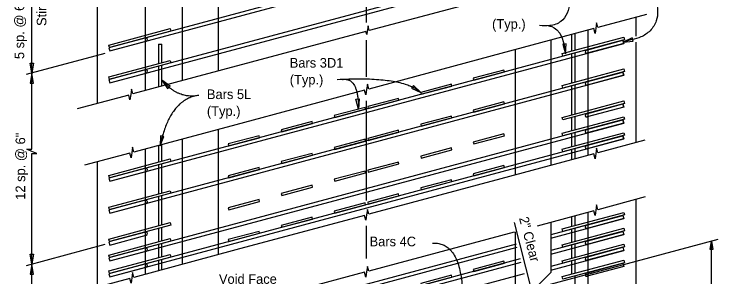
# Model space of a CAD drawing. Extents: x 0.8 to 30.4, y 0.3 to 18.9.
# Drawn here: x 19.16 to 30.22, y 8.31 to 12.43 of the extents above; entities that cross this region are included whole.
import ezdxf

# ---------------------------------------------------------------- set-up
doc = ezdxf.new("R2010")
doc.units = 0
for name, color, linetype in [('BeamConc', 7, 'Continuous'), ('BeamConc_h', 7, 'Continuous'), ('CL_Major', 7, 'Continuous'), ('Dimension', 7, 'Continuous'), ('Rebar', 7, 'Continuous'), ('Rebar_h', 7, 'Continuous'), ('TextStructures', 7, 'Continuous')]:
    doc.layers.add(name, color=color, linetype=linetype)

msp = doc.modelspace()

# ---------------------------------------------------------------- linework, layer by layer
at = {"layer": 'BeamConc'}
for p, q in [((20.473, 11.032), (20.473, 17.385)), ((21.807, 11.389), (21.807, 17.385)), ((28.932, 12.382), (28.932, 12.087)), ((27.598, 12.025), (27.598, 10.059)), ((28.932, 11.996), (28.932, 10.416)), ((21.807, 8.507), (21.807, 10.474)), ((20.473, 8.15), (20.473, 10.117)), ((28.932, 9.524), (28.932, 6.615)), ((27.598, 9.166), (27.598, 8.378)), ((27.598, 8.378), (27.348, 8.128))]:
    msp.add_line(p, q, dxfattribs=at)
at = {"layer": 'BeamConc_h'}
for p, q in [((22.369, 17.385), (22.369, 11.54)), ((21.223, 17.303), (21.223, 11.233)), ((28.182, 10.215), (28.182, 12.182)), ((27.036, 11.875), (27.036, 9.908)), ((22.369, 10.625), (22.369, 8.658)), ((21.223, 10.318), (21.223, 8.351)), ((28.182, 6.351), (28.182, 9.323)), ((27.036, 9.016), (27.036, 6.044))]:
    msp.add_line(p, q, dxfattribs=at)
at = {"layer": 'CL_Major'}
for p, q in [((24.702, 12.302), (24.702, 17.235)), ((24.702, 11.448), (24.702, 12.027)), ((24.702, 9.507), (24.702, 11.073)), ((24.702, 8.597), (24.702, 9.109))]:
    msp.add_line(p, q, dxfattribs=at)
at = {"layer": 'Dimension'}
for p, q in [((20.588, 11.816), (19.35, 11.485)), ((27.293, 8.113), (27.026, 9.166)), ((30.224, 8.898), (27.507, 8.17)), ((30.124, 6.872), (30.124, 8.872)), ((20.588, 8.816), (19.35, 8.485))]:
    msp.add_line(p, q, dxfattribs=at)
for points in [[(19.442, 11.509), (19.442, 17.646)], [(26.782, 12.723), (24.745, 12.177), (24.725, 12.252), (24.713, 12.168), (24.705, 12.116)], [(29.103, 12.428), (28.337, 12.223), (28.317, 12.298), (28.305, 12.214), (28.292, 12.131), (28.272, 12.206), (26.81, 11.814)], [(24.705, 12.116), (24.692, 12.163), (21.987, 11.438)], [(26.81, 11.814), (24.735, 11.258), (24.715, 11.333), (24.702, 11.25), (24.69, 11.166), (24.67, 11.241), (22.648, 10.699)], [(19.442, 8.509), (19.442, 10.246), (19.519, 10.246), (19.442, 10.28), (19.364, 10.314), (19.442, 10.314), (19.442, 11.509)], [(21.987, 11.438), (21.028, 11.181), (21.008, 11.256), (20.996, 11.172), (20.983, 11.089), (20.963, 11.164), (20.152, 10.946)], [(22.648, 10.699), (21.045, 10.27), (21.025, 10.345), (21.013, 10.261), (21, 10.178), (20.98, 10.253), (20.268, 10.062)], [(29.074, 10.454), (28.337, 10.257), (28.317, 10.331), (28.305, 10.248), (28.292, 10.164), (28.272, 10.239), (26.81, 9.847)], [(26.81, 9.847), (24.735, 9.292), (24.715, 9.367), (24.702, 9.283), (24.69, 9.199), (24.67, 9.274), (22.648, 8.733)], [(29.083, 9.564), (28.337, 9.364), (28.317, 9.439), (28.305, 9.356), (28.292, 9.272), (28.272, 9.347), (27.382, 9.108)], [(27.023, 9.012), (24.735, 8.399), (24.715, 8.474), (24.702, 8.391), (24.69, 8.307), (24.67, 8.382), (22.648, 7.84)], [(22.648, 8.733), (21.045, 8.303), (21.025, 8.378), (21.013, 8.295), (21, 8.211), (20.98, 8.286), (20.26, 8.093)], [(19.442, 3.464), (19.442, 7.546), (19.519, 7.546), (19.442, 7.58), (19.364, 7.614), (19.442, 7.614), (19.442, 8.509)]]:
    msp.add_lwpolyline(points, dxfattribs=at)
for points in [[(28.735, 11.996), (28.892, 12.012), (28.878, 12.063)], [(27.828, 11.812), (27.84, 11.97), (27.788, 11.965)], [(19.442, 11.509), (19.415, 11.666), (19.468, 11.666)], [(19.442, 11.509), (19.415, 11.353), (19.468, 11.353)], [(21.484, 11.399), (21.574, 11.269), (21.612, 11.306)], [(25.553, 11.206), (25.438, 11.315), (25.408, 11.271)], [(24.577, 10.945), (24.534, 11.097), (24.587, 11.103)], [(21.455, 10.366), (21.513, 10.514), (21.461, 10.525)], [(30.124, 8.871), (30.146, 8.738), (30.102, 8.738)], [(19.442, 8.509), (19.415, 8.666), (19.468, 8.666)], [(19.442, 8.509), (19.415, 8.353), (19.468, 8.353)]]:
    msp.add_lwpolyline(points, close=True, dxfattribs=at)
for points in [[(27.817, 13.338), (27.899, 12.616), (27.755, 12.319), (27.582, 12.253), (27.422, 12.253)], [(29.419, 12.835), (29.343, 12.835), (29.255, 12.772), (29.255, 12.645), (29.255, 12.328), (29.157, 12.174), (29.014, 12.076), (28.873, 12.034), (28.735, 11.996)]]:
    msp.add_spline(points, degree=3, dxfattribs=at)
for points, degree in [([(27.562, 12.248), (27.597, 12.246), (27.791, 12.231), (27.828, 11.812)], 3), ([(22.065, 11.158), (21.742, 11.094), (21.484, 11.399)], 2), ([(24.239, 11.409), (25.273, 11.465), (25.553, 11.206)], 2), ([(24.323, 11.409), (24.571, 11.449), (24.577, 10.945)], 2), ([(22.065, 11.158), (21.61, 11.103), (21.455, 10.366)], 2), ([(25.737, 8.841), (26.278, 8.87), (26.204, 7.649)], 2)]:
    msp.add_open_spline(points, degree=degree, dxfattribs=at)
at = {"layer": 'Rebar'}
for p, q in [((20.65, 11.949), (21.616, 12.208)), ((21.616, 12.208), (21.627, 12.168)), ((21.225, 12.06), (20.651, 11.906)), ((21.627, 12.168), (20.661, 11.909)), ((27.777, 11.814), (28.743, 12.073)), ((27.921, 12.112), (27.921, 11.853)), ((27.973, 12.126), (27.973, 11.867)), ((28.743, 12.073), (28.754, 12.033)), ((20.661, 11.909), (20.65, 11.949)), ((20.665, 11.856), (21.239, 12.01)), ((21.432, 11.964), (21.432, 11.659)), ((21.432, 11.964), (21.484, 11.964)), ((21.484, 11.673), (21.484, 11.964)), ((28.754, 12.033), (27.788, 11.774)), ((28.156, 11.871), (28.73, 12.025)), ((28.744, 11.975), (28.17, 11.821)), ((28.73, 12.025), (28.744, 11.975)), ((20.651, 11.906), (20.665, 11.856)), ((27.788, 11.774), (27.777, 11.814)), ((27.921, 11.81), (27.921, 11.353)), ((27.973, 11.824), (27.973, 11.367)), ((20.65, 11.449), (21.616, 11.708)), ((21.627, 11.668), (20.661, 11.409)), ((21.484, 11.303), (21.484, 11.629)), ((21.616, 11.708), (21.627, 11.668)), ((21.225, 11.56), (20.651, 11.406)), ((20.665, 11.356), (21.239, 11.51)), ((21.432, 11.616), (21.432, 11.289)), ((27.777, 11.314), (28.743, 11.573)), ((28.754, 11.533), (27.788, 11.274)), ((28.156, 11.371), (28.73, 11.525)), ((28.73, 11.525), (28.744, 11.475)), ((28.743, 11.573), (28.754, 11.533)), ((20.661, 11.409), (20.65, 11.449)), ((20.651, 11.406), (20.665, 11.356)), ((28.744, 11.475), (28.17, 11.321)), ((27.788, 11.274), (27.777, 11.314)), ((27.921, 11.31), (27.921, 10.853)), ((27.973, 11.324), (27.973, 10.867)), ((27.777, 10.814), (28.743, 11.073)), ((28.743, 11.073), (28.754, 11.033)), ((28.754, 11.033), (27.788, 10.774)), ((28.156, 10.871), (28.73, 11.025)), ((28.744, 10.975), (28.17, 10.821)), ((28.73, 11.025), (28.744, 10.975)), ((27.777, 10.564), (28.743, 10.823)), ((27.788, 10.774), (27.777, 10.814)), ((28.754, 10.783), (27.788, 10.524)), ((27.921, 10.81), (27.921, 10.603)), ((27.973, 10.824), (27.973, 10.617)), ((28.156, 10.621), (28.73, 10.775)), ((28.73, 10.775), (28.744, 10.725)), ((28.743, 10.823), (28.754, 10.783)), ((28.744, 10.725), (28.17, 10.571)), ((27.777, 10.314), (28.743, 10.573)), ((27.788, 10.524), (27.777, 10.564)), ((28.754, 10.533), (27.788, 10.274)), ((27.921, 10.56), (27.921, 10.353)), ((27.973, 10.574), (27.973, 10.367)), ((28.156, 10.371), (28.73, 10.525)), ((28.73, 10.525), (28.744, 10.475)), ((28.743, 10.573), (28.754, 10.533)), ((28.744, 10.475), (28.17, 10.321)), ((21.432, 10.373), (21.432, 10.113)), ((21.484, 10.127), (21.484, 10.387)), ((27.788, 10.274), (27.777, 10.314)), ((27.921, 10.31), (27.921, 10.145)), ((27.973, 10.324), (27.973, 10.159)), ((20.65, 9.903), (21.616, 10.162)), ((21.627, 10.122), (20.661, 9.863)), ((21.432, 10.07), (21.432, 9.613)), ((21.484, 9.627), (21.484, 10.083)), ((21.616, 10.162), (21.627, 10.122)), ((21.225, 10.014), (20.651, 9.86)), ((20.665, 9.81), (21.239, 9.964)), ((20.661, 9.863), (20.65, 9.903)), ((20.651, 9.86), (20.665, 9.81)), ((20.65, 9.403), (21.616, 9.662)), ((21.616, 9.662), (21.627, 9.622)), ((21.225, 9.514), (20.651, 9.36)), ((21.627, 9.622), (20.661, 9.363)), ((21.432, 9.57), (21.432, 9.113)), ((21.484, 9.127), (21.484, 9.583)), ((20.665, 9.31), (21.239, 9.464)), ((20.661, 9.363), (20.65, 9.403)), ((20.651, 9.36), (20.665, 9.31)), ((27.777, 9.064), (28.743, 9.323)), ((28.743, 9.323), (28.754, 9.283)), ((28.754, 9.283), (27.788, 9.024)), ((27.921, 9.253), (27.921, 9.103)), ((27.973, 9.267), (27.973, 9.117)), ((28.156, 9.121), (28.73, 9.275)), ((28.744, 9.225), (28.17, 9.071)), ((28.73, 9.275), (28.744, 9.225)), ((20.65, 8.903), (21.616, 9.162)), ((21.627, 9.122), (20.661, 8.863)), ((21.484, 8.877), (21.484, 9.083)), ((21.616, 9.162), (21.627, 9.122)), ((27.777, 8.814), (28.743, 9.073)), ((27.973, 9.074), (27.973, 8.867)), ((28.743, 9.073), (28.754, 9.033)), ((21.225, 9.014), (20.651, 8.86)), ((20.665, 8.81), (21.239, 8.964)), ((21.432, 9.07), (21.432, 8.863)), ((27.788, 9.024), (27.777, 9.064)), ((28.754, 9.033), (27.788, 8.774)), ((27.921, 9.06), (27.921, 8.853)), ((28.156, 8.871), (28.73, 9.025)), ((28.744, 8.975), (28.17, 8.821)), ((28.73, 9.025), (28.744, 8.975)), ((20.65, 8.653), (21.616, 8.912)), ((20.661, 8.863), (20.65, 8.903)), ((20.651, 8.86), (20.665, 8.81)), ((21.627, 8.872), (20.661, 8.613)), ((21.616, 8.912), (21.627, 8.872)), ((21.225, 8.764), (20.651, 8.61)), ((21.432, 8.82), (21.432, 8.613)), ((21.484, 8.627), (21.484, 8.833)), ((27.777, 8.564), (28.743, 8.823)), ((27.788, 8.774), (27.777, 8.814)), ((28.754, 8.783), (27.788, 8.524)), ((27.921, 8.81), (27.921, 8.603)), ((27.973, 8.824), (27.973, 8.617)), ((28.156, 8.621), (28.73, 8.775)), ((28.73, 8.775), (28.744, 8.725)), ((28.743, 8.823), (28.754, 8.783)), ((20.65, 8.403), (21.616, 8.662)), ((20.661, 8.613), (20.65, 8.653)), ((20.665, 8.56), (21.239, 8.714)), ((21.616, 8.662), (21.627, 8.622)), ((28.744, 8.725), (28.17, 8.571)), ((20.651, 8.61), (20.665, 8.56)), ((21.627, 8.622), (20.661, 8.363)), ((21.432, 8.57), (21.432, 8.407)), ((21.484, 8.421), (21.484, 8.583)), ((27.777, 8.314), (28.743, 8.573)), ((27.788, 8.524), (27.777, 8.564)), ((28.754, 8.533), (27.788, 8.274)), ((27.921, 8.56), (27.921, 8.353)), ((27.973, 8.574), (27.973, 8.367)), ((28.156, 8.371), (28.73, 8.525)), ((28.73, 8.525), (28.744, 8.475)), ((28.743, 8.573), (28.754, 8.533)), ((21.225, 8.514), (20.651, 8.36)), ((20.665, 8.31), (21.239, 8.464)), ((28.744, 8.475), (28.17, 8.321)), ((20.661, 8.363), (20.65, 8.403)), ((20.651, 8.36), (20.665, 8.31)), ((27.788, 8.274), (27.777, 8.314)), ((27.973, 8.324), (27.973, 8.018))]:
    msp.add_line(p, q, dxfattribs=at)
for points in [[(26.386, 11.397), (26.869, 11.526), (26.861, 11.557), (26.378, 11.427)], [(25.561, 11.176), (26.044, 11.305), (26.036, 11.335), (25.553, 11.206)], [(24.728, 10.953), (25.21, 11.082), (25.202, 11.112), (24.719, 10.983)], [(24.202, 10.812), (24.685, 10.941), (24.677, 10.971), (24.194, 10.842)], [(26.386, 10.897), (26.869, 11.026), (26.861, 11.057), (26.378, 10.927)], [(23.369, 10.589), (23.852, 10.718), (23.844, 10.748), (23.361, 10.619)], [(25.561, 10.676), (26.044, 10.805), (26.036, 10.835), (25.553, 10.706)], [(22.536, 10.365), (23.019, 10.495), (23.011, 10.525), (22.528, 10.396)], [(24.728, 10.453), (25.21, 10.582), (25.202, 10.612), (24.719, 10.483)], [(26.386, 10.397), (26.869, 10.526), (26.861, 10.557), (26.378, 10.427)], [(24.202, 10.312), (24.685, 10.441), (24.677, 10.471), (24.194, 10.342)], [(25.561, 10.176), (26.044, 10.305), (26.036, 10.335), (25.553, 10.206)], [(23.369, 10.089), (23.852, 10.218), (23.844, 10.248), (23.361, 10.119)], [(24.728, 9.953), (25.21, 10.082), (25.202, 10.112), (24.719, 9.983)], [(22.536, 9.865), (23.019, 9.995), (23.011, 10.025), (22.528, 9.896)], [(24.202, 9.812), (24.685, 9.941), (24.677, 9.971), (24.194, 9.842)], [(26.386, 9.897), (26.869, 10.026), (26.861, 10.057), (26.378, 9.927)], [(23.369, 9.589), (23.852, 9.718), (23.844, 9.748), (23.361, 9.619)], [(25.561, 9.676), (26.044, 9.805), (26.036, 9.835), (25.553, 9.706)], [(22.536, 9.365), (23.019, 9.495), (23.011, 9.525), (22.528, 9.396)], [(24.728, 9.453), (25.21, 9.582), (25.202, 9.612), (24.719, 9.483)], [(24.202, 9.312), (24.685, 9.441), (24.677, 9.471), (24.194, 9.342)], [(23.369, 9.089), (23.852, 9.218), (23.844, 9.248), (23.361, 9.119)], [(22.536, 8.865), (23.019, 8.995), (23.011, 9.025), (22.528, 8.896)], [(26.386, 8.397), (26.869, 8.526), (26.861, 8.557), (26.378, 8.427)], [(25.561, 8.176), (26.044, 8.305), (26.036, 8.335), (25.553, 8.206)]]:
    msp.add_lwpolyline(points, close=True, dxfattribs=at)
for centre, start, end in [((21.232, 12.035), 285, 105), ((28.163, 11.846), 105, 285), ((21.232, 11.535), 285, 105), ((28.163, 11.346), 105, 285), ((28.163, 10.846), 105, 285), ((28.163, 10.596), 105, 285), ((28.163, 10.346), 105, 285), ((21.232, 9.989), 285, 105), ((21.232, 9.489), 285, 105), ((28.163, 9.096), 105, 285), ((21.232, 8.989), 285, 105), ((28.163, 8.846), 105, 285), ((21.232, 8.739), 285, 105), ((28.163, 8.596), 105, 285), ((21.232, 8.489), 285, 105), ((28.163, 8.346), 105, 285)]:
    msp.add_arc(centre, 0.026, start, end, dxfattribs=at)
at = {"layer": 'Rebar_h'}
for p, q in [((28.744, 10.975), (28.73, 11.025)), ((28.73, 9.275), (27.598, 8.972)), ((27.598, 8.918), (28.744, 9.225)), ((28.73, 9.025), (27.598, 8.722)), ((27.598, 8.668), (28.744, 8.975)), ((21.238, 7.214), (27.066, 8.775)), ((27.053, 8.826), (21.627, 7.372)), ((28.73, 8.775), (27.598, 8.472)), ((27.598, 8.418), (28.744, 8.725)), ((21.238, 6.964), (27.129, 8.542)), ((27.115, 8.592), (21.627, 7.122)), ((27.178, 8.359), (21.627, 6.872))]:
    msp.add_line(p, q, dxfattribs=at)
for points in [[(28.741, 14.074), (20.651, 11.906), (20.665, 11.856), (28.754, 14.024)], [(28.741, 13.574), (20.651, 11.406), (20.665, 11.356), (28.754, 13.524)], [(28.73, 12.025), (20.651, 9.86), (20.665, 9.81), (28.744, 11.975)], [(28.73, 11.525), (20.651, 9.36), (20.665, 9.31), (28.744, 11.475)], [(28.73, 10.775), (20.651, 8.61), (20.665, 8.56), (28.744, 10.725)], [(28.73, 10.525), (20.651, 8.36), (20.665, 8.31), (28.744, 10.475)]]:
    msp.add_lwpolyline(points, close=True, dxfattribs=at)

# ---------------------------------------------------------------- texts
at = {"layer": 'Dimension'}
for s, p in [('(Typ.)', (26.674, 12.204)), ('Bars 3D1 ', (23.494, 11.594)), ('(Typ.)', (23.494, 11.33)), ('Bars 5L', (22.192, 11.101)), ('(Typ.)', (22.192, 10.837))]:
    msp.add_text(s, height=0.1512, dxfattribs=at).set_placement(p)
at = {"layer": 'TextStructures'}
for s, rotation, p in [('5 sp. @ 6" (along ℄ of Beam)', 90, (19.32, 11.728)), ('Stirrup Transition Zone ', 90, (19.669, 12.248)), ('12 sp. @ 6" ', 90, (19.336, 9.52)), ('2" Clear', 285, (27.096, 9.233))]:
    msp.add_text(s, height=0.1512, rotation=rotation, dxfattribs=at).set_placement(p)
for s, p in [('Bars 4C', (24.749, 8.79)), ('Void Face', (22.381, 8.201))]:
    msp.add_text(s, height=0.1512, dxfattribs=at).set_placement(p)

doc.saveas('drawing.dxf')
